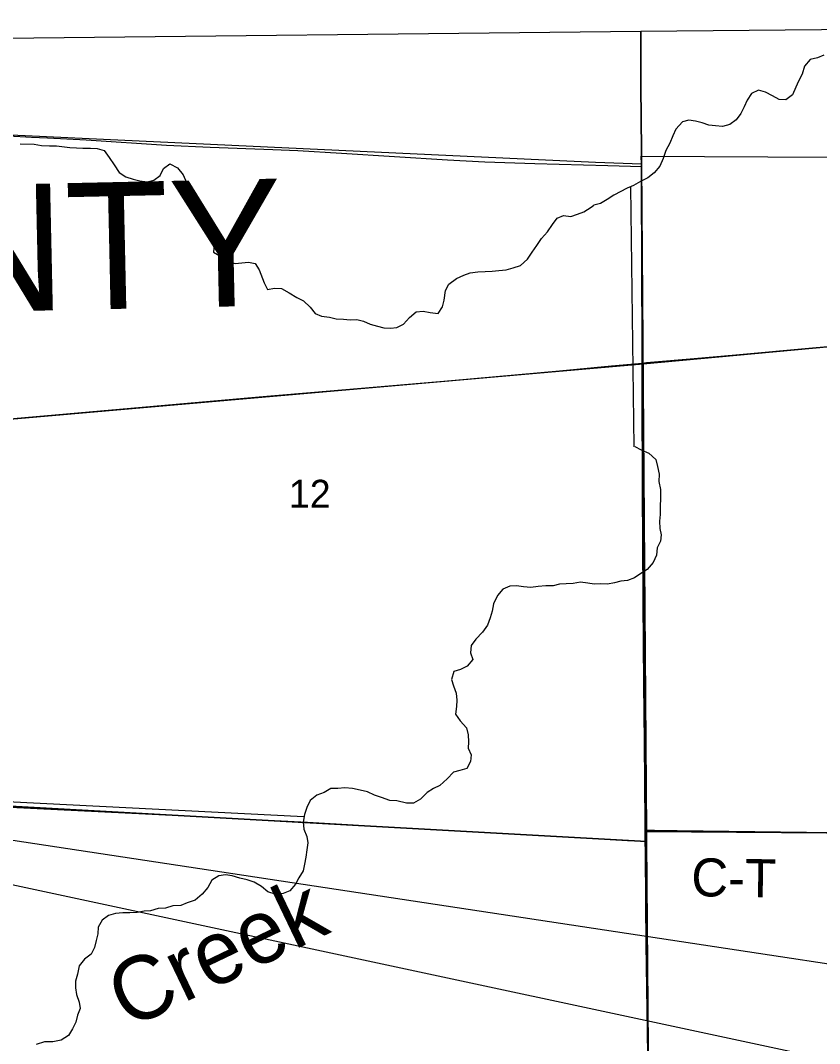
# Model space of a CAD drawing. Extents: x 0 to 34, y 0 to 22.
# Drawn here: x 6.55 to 7.743, y 19.3 to 20.828 of the extents above; entities that cross this region are included whole.
import ezdxf

# ---------------------------------------------------------------- set-up
doc = ezdxf.new("R2010")
doc.units = 0
for name, color, linetype in [('Default', 7, 'Continuous'), ('GM_X_County_Road', 7, 'Continuous'), ('GM_X_County_Road_Text', 7, 'Continuous'), ('GM_X_County_Text', 7, 'Continuous'), ('GM_X_Minor_River', 7, 'Continuous'), ('GM_X_Minor_River_Text', 7, 'Continuous'), ('GM_X_Rail_Line', 7, 'Continuous'), ('GM_X_Section', 7, 'Continuous'), ('GM_X_Section_Text', 7, 'Continuous'), ('GM_X_State_Route', 7, 'Continuous'), ('GM_X_Township_Road', 7, 'Continuous'), ('SH_Cut_Line', 7, 'Continuous'), ('SH_Text', 7, 'Continuous')]:
    doc.layers.add(name, color=color, linetype=linetype)

msp = doc.modelspace()

# ---------------------------------------------------------------- linework, layer by layer
at = {"layer": 'Default'}
for points in [[(7.4864, 19.2834), (7.4852, 19.3829), (7.4842, 19.4482), (7.4837, 19.5104), (7.4828, 19.5851), (7.4827, 19.6025), (7.4826, 19.6191), (7.4825, 19.6286), (7.4814, 19.7499), (7.4807, 19.837), (7.4794, 19.9583), (7.4793, 19.9676), (7.4783, 20.1263), (7.4779, 20.2725), (7.478, 20.3098), (7.4779, 20.3167), (7.4778, 20.3751), (7.4777, 20.4249), (7.4777, 20.4653), (7.4772, 20.5804), (7.4771, 20.61), (7.4771, 20.6333), (7.4761, 20.7297), (7.476, 20.811), (6.4789, 20.8005)], [(8.6079, 20.8216), (7.476, 20.811), (7.4761, 20.7297), (7.4771, 20.6333), (7.4771, 20.61), (7.4772, 20.5804), (7.4777, 20.4653), (7.4777, 20.4249), (7.4778, 20.3751), (7.4779, 20.3167), (7.478, 20.3098), (7.4779, 20.2725), (7.4783, 20.1263), (7.4793, 19.9676), (7.4794, 19.9583), (7.4807, 19.837), (7.4814, 19.7499), (7.4825, 19.6286), (7.4826, 19.6191), (7.4827, 19.6025), (7.4828, 19.5851), (7.4837, 19.5104), (7.4842, 19.4482), (7.4852, 19.3829), (7.4864, 19.2834)]]:
    msp.add_lwpolyline(points, dxfattribs=at)
at = {"layer": 'GM_X_County_Road'}
msp.add_line((7.4829, 19.602), (7.4828, 19.6185), dxfattribs=at)
for points in [[(7.4774, 20.6094), (7.4773, 20.6327), (7.4764, 20.7291), (7.4763, 20.8104)], [(7.4782, 20.3161), (7.478, 20.3745), (7.4779, 20.4243), (7.4779, 20.4647), (7.4775, 20.5798), (7.4774, 20.6094)], [(7.4828, 19.6185), (7.4828, 19.6281), (7.4817, 19.7494), (7.4809, 19.8365), (7.4796, 19.9578), (7.4795, 19.9671), (7.4785, 20.1257), (7.4781, 20.2719), (7.4782, 20.3092), (7.4782, 20.3161)], [(6.4906, 19.6548), (6.5039, 19.6545), (6.7366, 19.6428), (6.8359, 19.6379), (6.8701, 19.6362), (6.9787, 19.6306), (7.0469, 19.6267), (7.0872, 19.6241), (7.1927, 19.6183), (7.2516, 19.6148), (7.2826, 19.613), (7.3353, 19.6099), (7.4563, 19.603), (7.4829, 19.602)], [(7.4828, 19.6185), (7.4963, 19.6184), (7.5305, 19.6182), (7.7233, 19.6156), (8.0063, 19.6119), (8.056, 19.6111), (8.3201, 19.6098), (8.5938, 19.6077), (8.624, 19.6074)], [(7.4927, 18.6157), (7.4917, 18.6981), (7.4911, 18.7821), (7.4909, 18.8132), (7.4898, 18.922), (7.4894, 18.9873), (7.4891, 19.0278), (7.4886, 19.0713), (7.4872, 19.2237), (7.4867, 19.2828), (7.4854, 19.3824), (7.4845, 19.4477), (7.484, 19.5099), (7.483, 19.5845), (7.4829, 19.602)]]:
    msp.add_lwpolyline(points, dxfattribs=at)
at = {"layer": 'GM_X_Minor_River'}
for points in [[(7.7491, 20.776), (7.7396, 20.7719), (7.729, 20.7693), (7.7201, 20.7596), (7.7169, 20.7475), (7.7111, 20.7361), (7.7025, 20.7165), (7.6926, 20.709), (7.6823, 20.7099), (7.6726, 20.7149), (7.662, 20.7207), (7.6518, 20.7235), (7.6412, 20.7187), (7.635, 20.7085), (7.6303, 20.6987), (7.6252, 20.6889), (7.6183, 20.6791), (7.6087, 20.6724), (7.5981, 20.6691), (7.5875, 20.6703), (7.5776, 20.6712), (7.5678, 20.6747), (7.5576, 20.6775), (7.5478, 20.6787), (7.5383, 20.6765), (7.5283, 20.6652), (7.524, 20.6554), (7.5193, 20.6445), (7.5135, 20.6335), (7.5092, 20.6218), (7.5045, 20.6101), (7.496, 20.6), (7.4865, 20.5925), (7.4758, 20.5873), (7.4651, 20.5813), (7.4556, 20.5772), (7.4357, 20.5668), (7.4258, 20.5601), (7.4159, 20.5545), (7.406, 20.5518)], [(6.5499, 20.6434), (6.5708, 20.6432), (6.5817, 20.6412), (6.5935, 20.6403), (6.6041, 20.6406), (6.6238, 20.6381), (6.6336, 20.6376), (6.6435, 20.6368), (6.6545, 20.637), (6.6647, 20.6366), (6.6749, 20.6334), (6.6827, 20.6231), (6.6898, 20.612), (6.6973, 20.6009), (6.7074, 20.5944), (6.7184, 20.5905), (6.7282, 20.5881), (6.7392, 20.5869), (6.7491, 20.589), (6.7586, 20.5962), (6.7637, 20.6064), (6.7732, 20.6135), (6.7846, 20.6077), (6.7932, 20.5973), (6.798, 20.5859), (6.7948, 20.5761), (6.7932, 20.5647), (6.8041, 20.5555), (6.8062, 20.5448), (6.8118, 20.5353), (6.822, 20.5325), (6.8318, 20.5264), (6.8373, 20.5161), (6.8395, 20.5043), (6.8394, 20.4933), (6.8381, 20.4819), (6.8501, 20.4746), (6.8599, 20.4677), (6.8705, 20.4649), (6.8808, 20.4656), (6.8906, 20.467), (6.9005, 20.4646), (6.9064, 20.4551), (6.9138, 20.436), (6.919, 20.4261), (6.9292, 20.4279), (6.9398, 20.4274), (6.9511, 20.4212), (6.9628, 20.4139)], [(7.4606, 20.5794), (7.4658, 20.191)], [(6.9628, 20.4139), (6.9726, 20.4092), (6.9827, 20.3996), (6.9898, 20.3901), (6.9997, 20.3862), (7.0114, 20.3846), (7.0212, 20.3822), (7.0322, 20.3817), (7.0424, 20.3805), (7.0523, 20.3811), (7.0621, 20.3784), (7.0723, 20.3741), (7.0829, 20.3713), (7.0927, 20.3686), (7.1026, 20.3681), (7.1121, 20.3691), (7.122, 20.374), (7.1308, 20.3841), (7.1408, 20.3924), (7.151, 20.3938), (7.1616, 20.3914), (7.1737, 20.3902), (7.1803, 20.4003), (7.1827, 20.4102), (7.1847, 20.4242), (7.1894, 20.434), (7.2008, 20.4422), (7.2119, 20.4475), (7.2214, 20.4508), (7.2328, 20.4522), (7.2438, 20.4528), (7.254, 20.4531), (7.2643, 20.4541), (7.2753, 20.4555), (7.2856, 20.4585), (7.2966, 20.4618), (7.3069, 20.4712), (7.3139, 20.4817), (7.3208, 20.4915), (7.3278, 20.5021), (7.337, 20.5122), (7.3443, 20.5228), (7.3512, 20.5326), (7.3607, 20.5363), (7.3717, 20.535), (7.3816, 20.5383), (7.3911, 20.5417), (7.4018, 20.5488), (7.406, 20.5518)], [(7.467, 20.1914), (7.4768, 20.1867), (7.4881, 20.1813), (7.4982, 20.1721), (7.5011, 20.1614), (7.5036, 20.15), (7.5027, 20.139), (7.5052, 20.1272), (7.5054, 20.117), (7.5048, 20.0996), (7.5047, 20.0901), (7.5038, 20.0798), (7.5045, 20.0692), (7.5066, 20.0597), (7.5053, 20.0499), (7.5003, 20.0401), (7.4994, 20.0294), (7.4943, 20.0181), (7.4855, 20.008), (7.4759, 20.0016), (7.4664, 19.9956), (7.4561, 19.9912), (7.4462, 19.9902), (7.4367, 19.988), (7.4265, 19.9858), (7.4159, 19.9863), (7.4064, 19.9857), (7.397, 19.9876)], [(7.397, 19.9876), (7.3861, 19.9889), (7.375, 19.9871), (7.3644, 19.9864), (7.3549, 19.9858), (7.3454, 19.9836), (7.3344, 19.9833), (7.323, 19.9823), (7.312, 19.9809), (7.3011, 19.9821), (7.2905, 19.9834), (7.2806, 19.9831), (7.2699, 19.9786), (7.2622, 19.9688), (7.256, 19.9564), (7.254, 19.9454), (7.2513, 19.9356), (7.2473, 19.9246), (7.24, 19.9144), (7.2297, 19.9039), (7.2227, 19.8941), (7.2219, 19.8835), (7.2252, 19.8736), (7.2171, 19.8634), (7.2068, 19.8586), (7.1969, 19.8557), (7.1937, 19.8435), (7.1967, 19.834), (7.2003, 19.823), (7.2014, 19.8127), (7.2009, 19.8032), (7.1996, 19.7919), (7.2063, 19.7819), (7.2157, 19.7716), (7.2186, 19.7609), (7.2189, 19.7507), (7.2184, 19.7412), (7.2228, 19.7309), (7.222, 19.7211), (7.2162, 19.7105), (7.2059, 19.7079), (7.1964, 19.705), (7.1868, 19.6952), (7.1761, 19.6855), (7.1666, 19.681), (7.157, 19.675), (7.1474, 19.6649), (7.1367, 19.6589), (7.1261, 19.659), (7.1121, 19.6622), (7.1015, 19.6631), (7.0891, 19.6674), (7.0785, 19.6709), (7.0683, 19.6759), (7.0573, 19.6783), (7.0456, 19.6807), (7.0343, 19.6816), (7.024, 19.6809), (7.0134, 19.6806), (7.0035, 19.675), (6.9924, 19.6706), (6.9825, 19.6631), (6.9778, 19.6525), (6.9739, 19.6419), (6.9719, 19.6306), (6.9729, 19.6199), (6.9774, 19.6093), (6.9791, 19.5994), (6.9775, 19.5892), (6.9759, 19.5782), (6.9739, 19.5676), (6.9722, 19.5577), (6.9657, 19.5475), (6.9607, 19.5377), (6.9522, 19.5279), (6.9423, 19.5239), (6.9317, 19.5224), (6.9196, 19.5264), (6.9098, 19.5344), (6.8989, 19.541), (6.8883, 19.5445), (6.8774, 19.5469), (6.866, 19.5504), (6.8562, 19.5517), (6.8463, 19.5506), (6.836, 19.5439), (6.8298, 19.5329), (6.8214, 19.5228), (6.811, 19.5142), (6.7992, 19.5101), (6.7893, 19.506), (6.7776, 19.5054), (6.7669, 19.5021), (6.7556, 19.5018), (6.7445, 19.4981), (6.7347, 19.4978), (6.7244, 19.4957), (6.7134, 19.495), (6.7032, 19.4951), (6.6922, 19.4941), (6.6815, 19.4911)], [(6.9733, 19.6383), (6.4904, 19.6627), (5.9957, 19.6619)], [(6.6815, 19.4911), (6.672, 19.484), (6.6662, 19.4738), (6.6657, 19.4636), (6.6633, 19.4538), (6.6609, 19.4435), (6.6559, 19.4333), (6.6459, 19.4258), (6.6379, 19.4161), (6.6351, 19.4036), (6.6323, 19.393), (6.6322, 19.3831), (6.6336, 19.3732), (6.6377, 19.3618), (6.6395, 19.3523), (6.6352, 19.3421), (6.6328, 19.3319), (6.6278, 19.3217), (6.622, 19.3118), (6.6109, 19.3051), (6.5987, 19.3026), (6.5862, 19.3023), (6.5737, 19.2987)]]:
    msp.add_lwpolyline(points, dxfattribs=at)
at = {"layer": 'GM_X_Rail_Line'}
msp.add_lwpolyline([(2.1, 19.6449), (2.4687, 19.6463), (3.2362, 19.6474), (3.7244, 19.6491), (5.0197, 19.6574), (5.4852, 19.6574), (5.5146, 19.6675), (5.5588, 19.7034), (6.1514, 20.0969), (6.291, 20.193), (6.3333, 20.2132), (6.3747, 20.2169), (6.4833, 20.2279), (7.4795, 20.3149), (8.1518, 20.3773), (8.7379, 20.4271), (8.9, 20.4441)], dxfattribs=at)
at = {"layer": 'GM_X_Section'}
for points in [[(6.4819, 20.6594), (7.4085, 20.616), (7.4769, 20.6134), (7.4843, 19.6166), (7.4844, 19.6018), (6.4898, 19.6568)], [(7.4769, 20.6134), (7.4767, 20.6252), (8.611, 20.6193), (8.626, 19.6083), (7.4843, 19.6166)], [(6.4898, 19.6568), (7.4844, 19.6018), (7.4927, 18.6151), (7.4929, 18.6076), (6.4992, 18.6508)], [(7.4843, 19.6166), (8.626, 19.6083), (8.6395, 18.6159), (7.4927, 18.6151), (7.4844, 19.6018)]]:
    msp.add_lwpolyline(points, close=True, dxfattribs=at)
at = {"layer": 'GM_X_State_Route'}
msp.add_line((7.4323, 20.3119), (7.4782, 20.3161), dxfattribs=at)
for points in [[(7.4782, 20.3161), (7.4846, 20.3167), (7.5559, 20.323), (7.6178, 20.3286), (7.7324, 20.3388), (7.8006, 20.3449), (7.878, 20.3519), (7.9647, 20.3593), (8.0174, 20.364), (8.067, 20.3682), (8.1351, 20.3744), (8.259, 20.3854), (8.3055, 20.3899), (8.4262, 20.401), (8.5099, 20.4087), (8.5904, 20.4154), (8.6122, 20.4173), (8.6173, 20.4178), (8.7876, 20.4331), (8.8557, 20.4398), (8.9, 20.4439)], [(6.5398, 20.2331), (6.6358, 20.2418), (6.7319, 20.2504), (6.9178, 20.2665), (6.989, 20.2726), (7.1935, 20.2902), (7.3546, 20.3047), (7.4323, 20.3119)]]:
    msp.add_lwpolyline(points, dxfattribs=at)
at = {"layer": 'GM_X_Township_Road'}
msp.add_lwpolyline([(6.4817, 20.6572), (6.498, 20.6566), (6.5323, 20.6552), (6.5665, 20.6536), (6.5905, 20.6522), (6.6483, 20.6492), (6.7683, 20.6417), (6.8335, 20.6387), (6.9268, 20.635), (6.964, 20.6333), (7.0292, 20.6294), (7.1875, 20.6196), (7.2434, 20.6168), (7.318, 20.6142), (7.4267, 20.6111), (7.4774, 20.6094)], dxfattribs=at)
at = {"layer": 'SH_Cut_Line'}
msp.add_lwpolyline([(2.1, 20.6957), (2.1, 14.1), (8.9, 14.1), (8.9, 20.8277), (8.6079, 20.8216), (7.476, 20.811), (6.4789, 20.8005), (5.4741, 20.7803), (4.4698, 20.7584), (3.7151, 20.7343), (2.4566, 20.7022)], close=True, dxfattribs=at)
at = {"layer": 'SH_Text'}
msp.add_lwpolyline([(5.4846, 19.763), (9.956, 18.8047), (9.956, 19.0851)], close=True, dxfattribs=at)

# ---------------------------------------------------------------- texts
at = {"layer": 'GM_X_County_Road_Text'}
msp.add_text('C-T', height=0.05682, rotation=359.1454, dxfattribs=at).set_placement((7.551, 19.52))
at = {"layer": 'GM_X_County_Text'}
msp.add_text('FULTON COUNTY', height=0.189394, rotation=1.2494, dxfattribs=at).set_placement((4.7905, 20.3554))
at = {"layer": 'GM_X_Minor_River_Text'}
msp.add_text('Creek', height=0.09475, rotation=25.5938, dxfattribs=at).set_placement((6.7107, 19.3206))
at = {"layer": 'GM_X_Section_Text'}
msp.add_text('12', height=0.04186, rotation=0, dxfattribs=at).set_placement((6.9508, 20.0999))

doc.saveas('drawing.dxf')
